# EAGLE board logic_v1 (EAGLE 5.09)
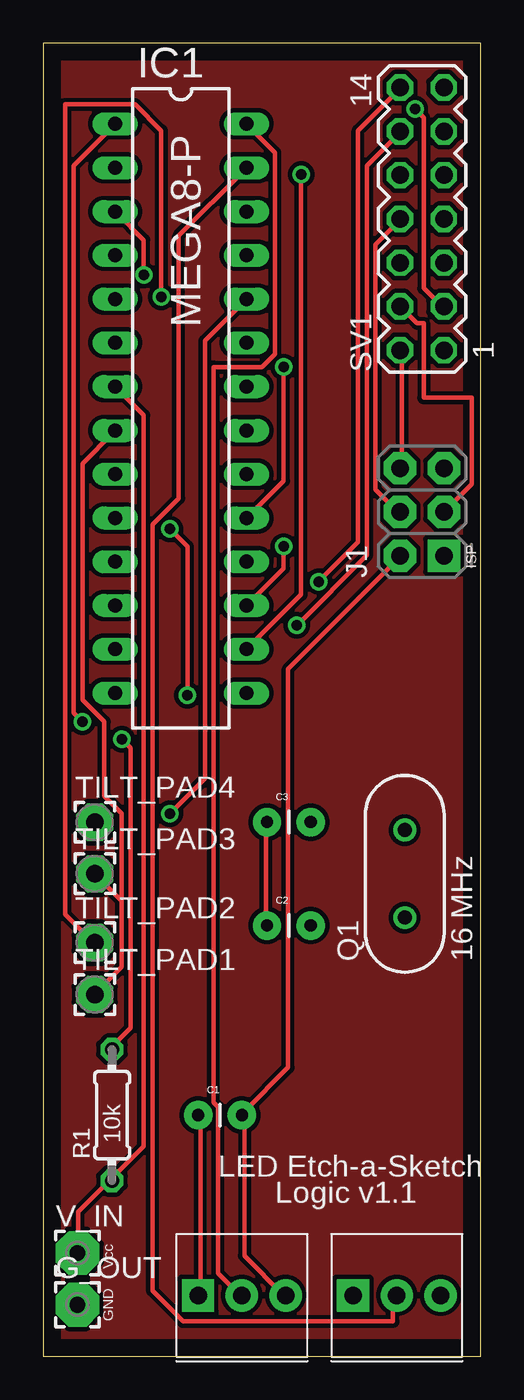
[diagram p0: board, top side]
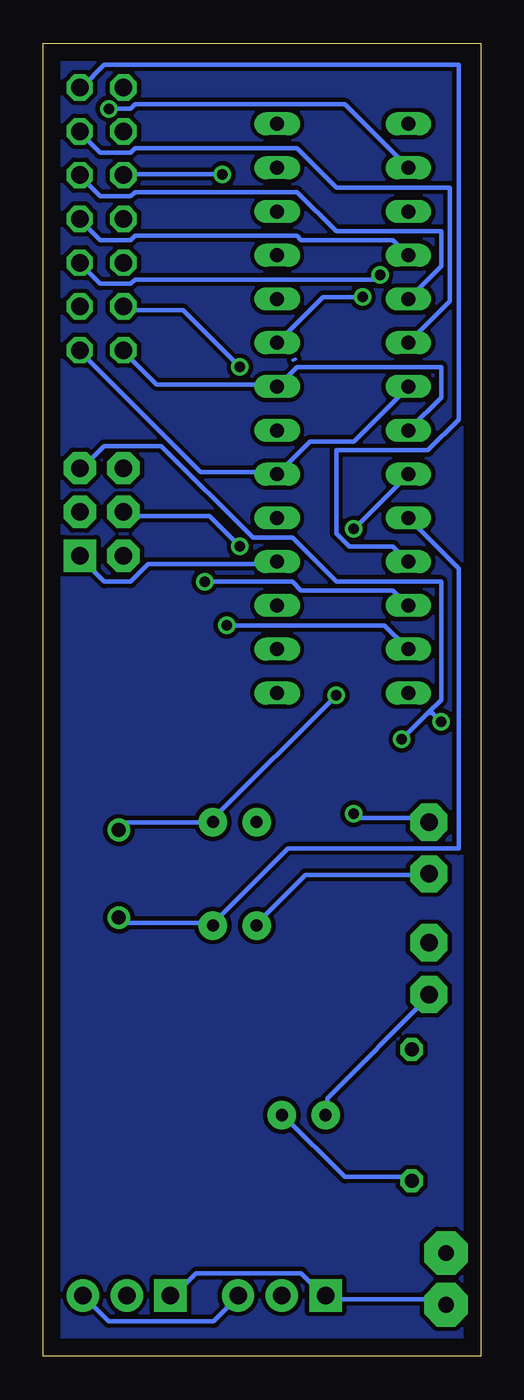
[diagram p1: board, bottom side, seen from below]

Size 25.4 x 76.2 mm. Coordinates in mm from the lower left corner, seen from the top.
Outline: 0,0 25.4,0 25.4,76.2 0,76.2 0,0
Copper layers (1*16): Top 0.035mm / dielectric 1.5mm / Bottom 0.035mm
Design rules "default": minimum track width 10mil, minimum drill 24mil, track to track 8mil, track to pad 8mil, pad to pad 8mil, via to via 8mil, smd to smd 8mil, copper to edge 40mil, drill to drill 8mil, minimum pad ring 10mil, minimum via ring 8mil, stop-mask expansion 4mil, vias tented up to drill 0mil, thermal gap 10mil

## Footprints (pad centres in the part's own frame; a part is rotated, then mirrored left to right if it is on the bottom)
CAP-PTH-SMALL = drill 0.7 pad 1.651 round: 1 0,0; 2 2.54,0
2,54/0,9 = drill 0.914 pad 2.54 octagon: 1 0,0
DIL28-3 = drill 0.813 long: 1 -16.51,-3.81; 2 -13.97,-3.81; 3 -11.43,-3.81; 4 -8.89,-3.81; 5 -6.35,-3.81; 6 -3.81,-3.81; 7 -1.27,-3.81; 8 1.27,-3.81; 9 3.81,-3.81; 10 6.35,-3.81; 11 8.89,-3.81; 12 11.43,-3.81; 13 13.97,-3.81; 14 16.51,-3.81; 15 16.51,3.81; 16 13.97,3.81; 17 11.43,3.81; 18 8.89,3.81; 19 6.35,3.81; 20 3.81,3.81; 21 1.27,3.81; 22 -1.27,3.81; 23 -3.81,3.81; 24 -6.35,3.81; 25 -8.89,3.81; 26 -11.43,3.81; 27 -13.97,3.81; 28 -16.51,3.81
2X3-NS = drill 1.016 pad 1.88 square: 1 -2.54,-1.27 | drill 1.016 pad 1.88 octagon: 2 -2.54,1.27; 3 0,-1.27; 4 0,1.27; 5 2.54,-1.27; 6 2.54,1.27
HC49US = drill 0.813 round: 1 -2.54,0; 2 2.54,0
0204/7 = drill 0.813 octagon: 1 -3.81,0; 2 3.81,0
MA07-2 = drill 1.016 octagon: 1 -7.62,-1.27; 2 -7.62,1.27; 3 -5.08,-1.27; 4 -5.08,1.27; 5 -2.54,-1.27; 6 -2.54,1.27; 7 0,-1.27; 8 0,1.27; 9 2.54,-1.27; 10 2.54,1.27; 11 5.08,-1.27; 12 5.08,1.27; 13 7.62,-1.27; 14 7.62,1.27
2,15/1,0 = drill 1.016 pad 2.159 octagon: 1 0,0
3362U = drill 1.016 pad 1.88 square: P$1 0,2.54 | drill 1.016 pad 1.88 round: P$2 2.54,2.54; P$3 5.08,2.54

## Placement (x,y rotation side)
C1  0.1uF  [CAP-PTH-SMALL]  9,14 0 top
C2  22pF  [CAP-PTH-SMALL]  13,25 0 top
C3  22pF  [CAP-PTH-SMALL]  13,31 0 top
G_OUT  WIREPAD2,54/0,9  [2,54/0,9]  2,3 0 top
IC1  MEGA8-P  [DIL28-3]  8,55 270 top
J1  AVR_SPI_PRG_6NS  [2X3-NS]  22,49 90 top
Q1  16 MHz  [HC49US]  21,28 90 top
R1  10k  [0204/7]  4,14 90 top
SV1  [MA07-2]  22,66 90 top
TILT_PAD1  [2,15/1,0]  3,21 0 top
TILT_PAD2  [2,15/1,0]  3,24 0 top
TILT_PAD3  [2,15/1,0]  3,28 0 top
TILT_PAD4  [2,15/1,0]  3,31 0 top
U$10  [3362U]  18,1 0 top
U$11  [3362U]  9,1 0 top
V_IN  WIREPAD2,54/0,9  [2,54/0,9]  2,6 0 top

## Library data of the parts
C1-C3 J1 Q1 U$10 U$11 = SparkFun
G_OUT TILT_PAD1-TILT_PAD4 V_IN = wirepad
IC1 = atmel
R1 = resistor
SV1 = con-lstb

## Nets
5V: C1.2 IC1.7 IC1.20 J1.2 R1.1 SV1.1 U$10.P$3 U$11.P$3 V_IN.1
D0: IC1.2 SV1.3
D1: IC1.3 SV1.5
D2: IC1.4 SV1.7
D3: IC1.5 SV1.9
D4: IC1.6 SV1.11
D5: IC1.11 SV1.13
D6: IC1.12 SV1.14
D7: IC1.13 SV1.12
GND: C1.1 C2.1 C3.1 G_OUT.1 IC1.8 IC1.22 J1.6 SV1.2 TILT_PAD1.1 TILT_PAD3.1 U$10.P$1 U$11.P$1
ISP_MISO: IC1.18 J1.1
ISP_MOSI: IC1.17 J1.4 SV1.8
ISP_RESET: IC1.1 J1.5 R1.2
ISP_SCK: IC1.19 J1.3 SV1.4
N$1: IC1.16 SV1.10
N$9: C3.2 IC1.9 Q1.2
N$10: C2.2 IC1.10 Q1.1
N$106: IC1.23 TILT_PAD2.1
N$107: IC1.24 TILT_PAD4.1
N$108: IC1.28 U$11.P$2
N$109: IC1.27 U$10.P$2

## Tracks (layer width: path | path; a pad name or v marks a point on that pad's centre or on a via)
5V
  Top 0.254: V_IN.1 2.03,6.1 2.03,8.38 3.81,10.16 R1.1 4.06,10.41 5.84,12.19 5.84,54.61 4.32,56.13 IC1.7 | U$11.P$3 13.97,3.56 11.68,5.84 11.68,13.97 C1.2 11.68,14.22 14.22,16.76 14.22,39.88 20.57,46.23 J1.2
  Bottom 0.254: IC1.7 4.32,56.13 7.37,53.09 9.91,53.09 11.68,51.31 IC1.20 11.94,51.31 16.26,51.31 23.11,58.17 SV1.1 | C1.2 11.43,13.97 7.87,10.41 4.06,10.41 R1.1 | U$10.P$3 22.86,3.3 21.59,2.03 15.49,2.03 14.22,3.3 U$11.P$3
D0  (via drill 0.61)
  Top 0.254: v21.59,72.39 22.1,71.88 22.1,61.98 23.11,60.96 SV1.3
  Bottom 0.254: v21.59,72.39 20.32,72.39 20.07,72.64 7.87,72.64 4.32,69.09 IC1.2
D1  (via drill 0.61)
  Top 0.254: v5.84,62.74 5.84,64.77 4.32,66.29 IC1.3
  Bottom 0.254: v5.84,62.74 6.1,62.48 20.07,62.48 20.32,62.23 22.1,62.23 23.11,63.25 SV1.5
D2
  Bottom 0.254: IC1.4 4.32,64.01 5.08,64.77 10.41,64.77 10.67,65.02 20.07,65.02 20.32,64.77 22.1,64.77 23.11,65.79 SV1.7
D3
  Bottom 0.254: IC1.5 4.06,61.47 2.29,63.25 2.29,65.28 8.38,65.28 10.67,67.56 20.07,67.56 20.32,67.31 22.1,67.31 23.11,68.33 SV1.9
D4
  Bottom 0.254: IC1.6 4.06,58.93 1.78,61.21 1.78,67.82 8.38,67.82 10.67,70.1 20.07,70.1 20.32,69.85 22.1,69.85 23.11,70.87 SV1.11
D5
  Bottom 0.254: IC1.11 4.32,46.23 5.08,46.99 7.62,46.99 8.38,47.75 8.38,52.58 3.05,52.58 1.27,54.36 1.27,74.93 21.84,74.93 23.11,73.66 SV1.13
D6  (via drill 0.61)
  Top 0.254: v16,44.96 18.29,47.24 18.29,71.12 20.57,73.41 SV1.14
  Bottom 0.254: v16,44.96 10.92,44.96 10.41,44.45 5.08,44.45 4.32,43.69 IC1.12
D7  (via drill 0.61)
  Top 0.254: v14.73,42.42 18.8,46.48 18.8,69.09 20.57,70.87 SV1.12
  Bottom 0.254: v14.73,42.42 5.59,42.42 4.32,41.15 IC1.13
GND
  Top 0.254: SV1.2 20.83,58.17 20.83,51.56 J1.6 | C2.1 12.95,25.15 12.95,30.99 C3.1 | 4.57,26.42 4.57,22.61 3.05,21.08 TILT_PAD1.1 | 4.57,26.42 3.05,27.94 TILT_PAD3.1 | C1.1 9.14,13.97 9.14,3.56 U$11.P$1 | 4.57,26.42 4.57,31.5 3.56,32.51 3.56,36.83 2.29,38.1 2.29,51.82 4.06,53.59 IC1.8
  Bottom 0.254: IC1.8 4.06,53.85 2.29,55.63 2.29,57.4 10.67,57.4 11.68,56.39 IC1.22 11.94,56.39 18.8,56.39 20.57,58.17 SV1.2 | C2.1 12.95,25.15 10.16,27.94 3.05,27.94 TILT_PAD3.1 | U$10.P$1 17.78,3.56 16.51,4.83 10.41,4.83 9.14,3.56 U$11.P$1 8.89,3.3 2.29,3.3 2.03,3.05 G_OUT.1 | TILT_PAD1.1 3.05,20.83 8.89,14.99 8.89,14.22 C1.1
ISP_MISO
  Bottom 0.254: IC1.18 11.94,45.97 19.3,45.97 20.32,44.96 21.84,44.96 23.11,46.23 J1.1
ISP_MOSI  (via drill 0.61)
  Top 0.254: v13.97,46.99 13.97,45.72 11.94,43.69 IC1.17 | SV1.8 20.57,65.79 19.3,64.52 19.3,50.29 20.57,49.02 J1.4
  Bottom 0.254: v13.97,46.99 15.75,48.77 20.57,48.77 J1.4
ISP_RESET  (via drill 0.61)
  Top 0.254: v4.57,35.81 5.08,35.31 5.08,19.05 4.06,18.03 R1.2 | v2.29,36.83 1.78,37.34 1.78,69.09 4.06,71.37 IC1.1
  Bottom 0.254: 3.05,37.34 2.29,38.1 2.29,44.96 8.38,44.96 10.92,47.5 13.21,47.5 18.54,52.83 21.84,52.83 23.11,51.56 J1.5 | v4.57,35.81 3.05,37.34 | v2.29,36.83 2.79,37.34 3.05,37.34
ISP_SCK  (via drill 0.61)
  Top 0.254: v13.97,57.4 13.97,50.8 11.94,48.77 IC1.19 | J1.3 24.89,50.62 24.89,55.63 22.1,55.63 22.1,59.94 21.71,59.94 SV1.4
  Bottom 0.254: v13.97,57.4 17.27,60.71 20.57,60.71 SV1.4
N$1  (via drill 0.61)
  Top 0.254: v14.99,68.58 14.99,44.2 11.94,41.15 IC1.16
  Bottom 0.254: v14.99,68.58 20.57,68.58 SV1.10
N$2
  pour Top (isolate 0.254): 0,76.2 25.4,76.2 25.4,0 0,0
N$3
  pour Bottom (isolate 0.254): 0,76.2 25.4,76.2 25.4,0 0,0
N$4
  Bottom 0.203: 10.74,57.86 10.9,57.81
N$9  (via drill 0.61)
  Top 0.254: v7.37,48.01 8.38,46.99 v8.38,38.35
  Bottom 0.254: Q1.2 20.83,30.73 20.57,30.99 15.75,30.99 C3.2 15.49,31.24 v8.38,38.35 | v7.37,48.01 4.32,51.05 IC1.9
N$10
  Bottom 0.254: Q1.1 20.83,25.4 20.57,25.15 15.75,25.15 C2.2 15.49,25.15 11.18,29.46 1.27,29.46 1.27,45.72 4.06,48.51 IC1.10
N$106  (via drill 0.61)
  Top 0.254: v6.86,61.47 6.86,71.12 5.33,72.64 1.27,72.64 1.27,25.65 2.79,24.13 TILT_PAD2.1
  Bottom 0.254: v6.86,61.47 9.14,61.47 11.68,58.93 IC1.23
N$107  (via drill 0.61)
  Top 0.254: v7.37,31.5 9.4,33.53 9.4,58.93 11.68,61.21 IC1.24
  Bottom 0.254: v7.37,31.5 7.11,31.24 3.05,31.24 TILT_PAD4.1
N$108
  Top 0.254: IC1.28 11.94,71.37 13.46,69.85 13.46,58.17 12.7,57.4 9.91,57.4 9.91,14.73 10.16,14.48 10.16,4.83 11.43,3.56 U$11.P$2
N$109
  Top 0.254: IC1.27 11.68,68.83 7.87,65.02 7.87,49.78 6.35,48.26 6.35,3.81 8.13,2.03 20.32,2.03 20.32,3.3 U$10.P$2

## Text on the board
_tsilk: MEGA8-P | ISP | C3 | C2 | 16 MHz | C1 | 10k | R1 | LED Etch-a-Sketch | Logic v1.1 | WIREPAD2,54/0,9 | Vcc | WIREPAD2,54/0,9 | GND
